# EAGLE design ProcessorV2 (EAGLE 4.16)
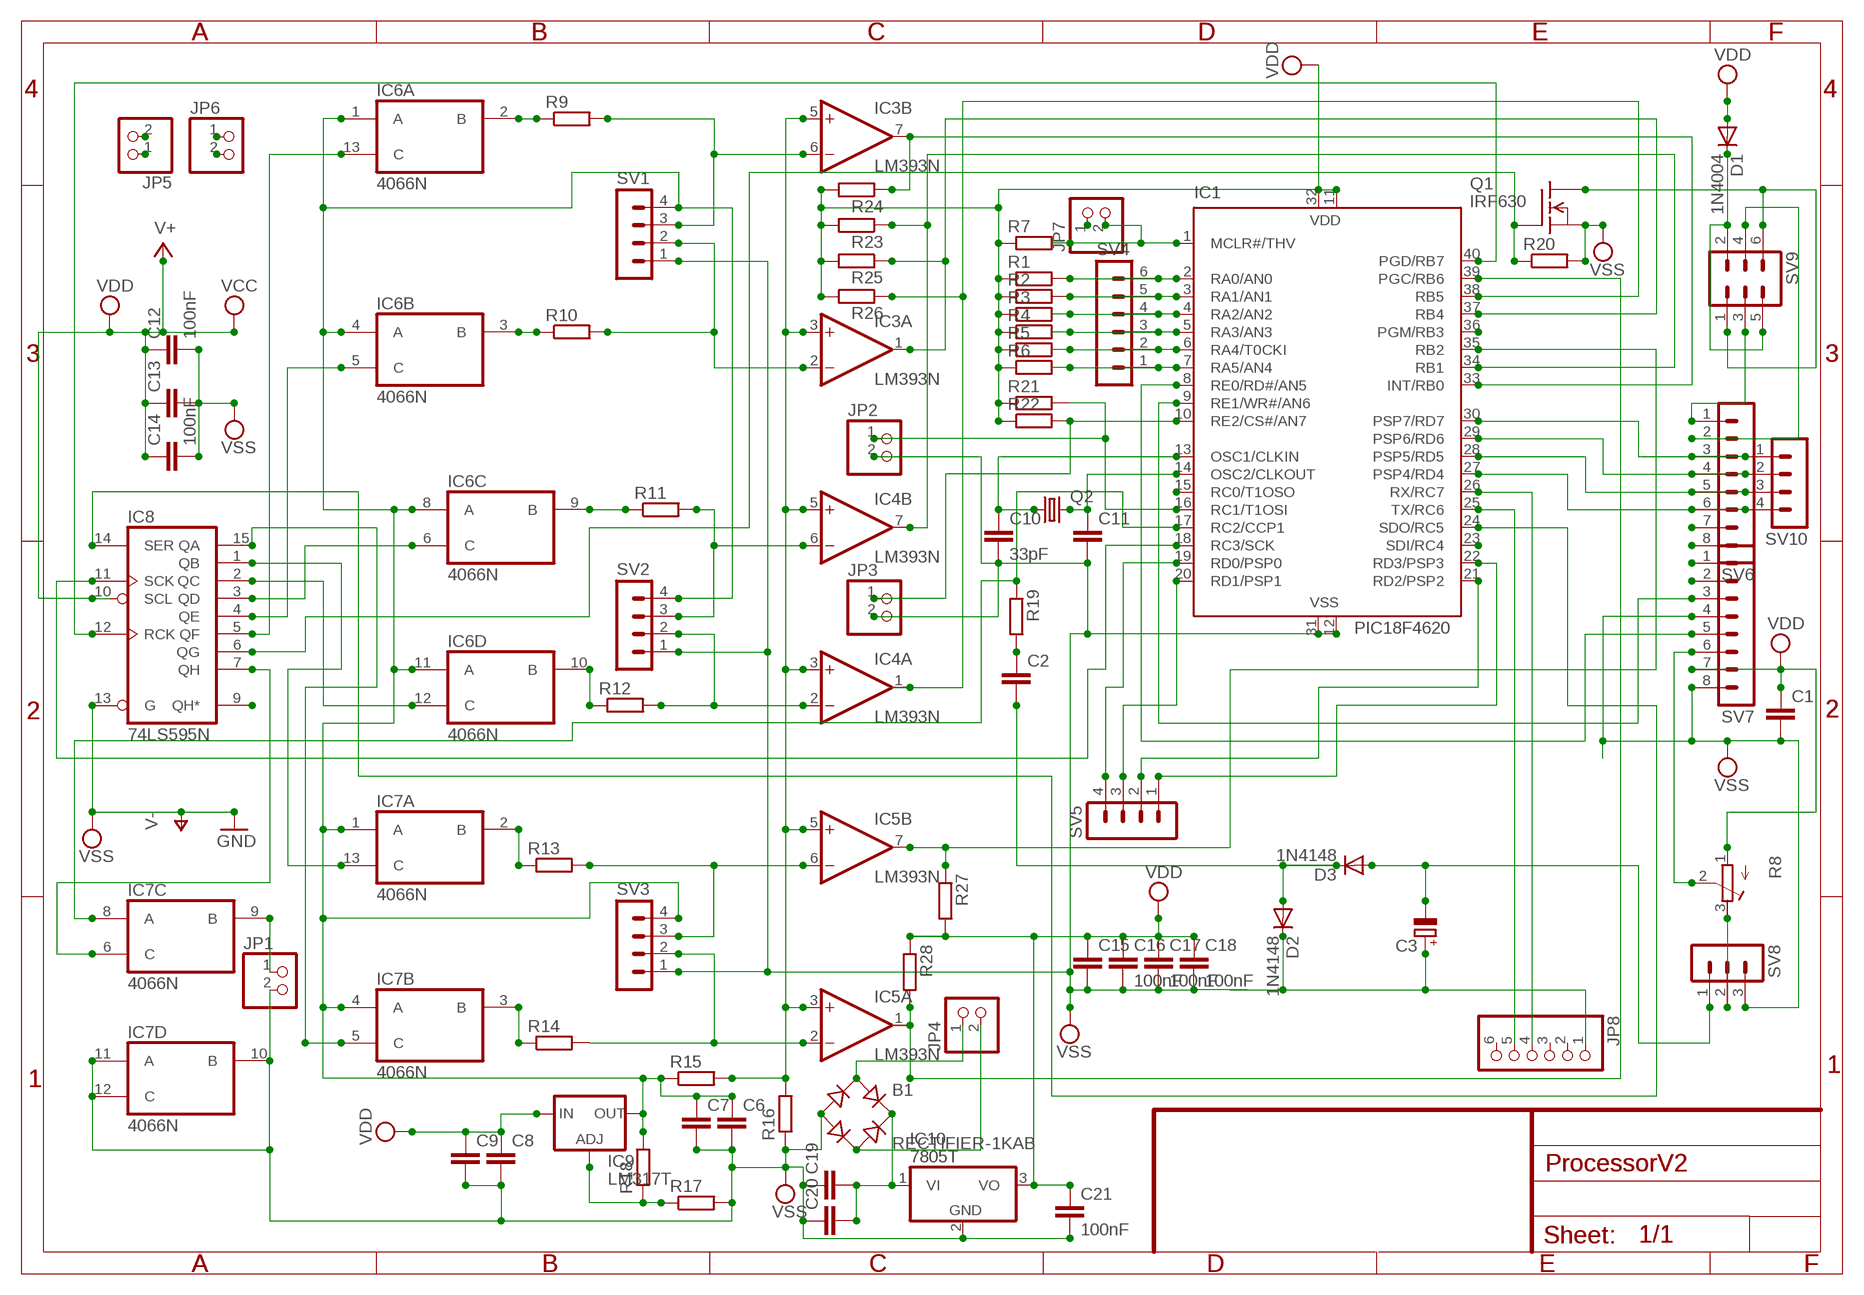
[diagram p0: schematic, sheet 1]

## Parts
B1  RECTIFIER-1KAB  [1KAB]
C1  C-EU050-024X044  [C050-024X044]
C2  C-EU025-030X050  [C025-030X050]
C3  CPOL-EUE2.5-6  [E2,5-6]
C6  C-EU050-024X044  [C050-024X044]
C7  C-EU050-024X044  [C050-024X044]
C8  C-EU050-024X044  [C050-024X044]
C9  C-EU050-024X044  [C050-024X044]
C10  33pF  C-EU050-024X044  [C050-024X044]
C11  C-EU050-024X044  [C050-024X044]
C12  100nF  C-EU050-024X044  [C050-024X044]
C13  C-EU050-024X044  [C050-024X044]
C14  100nF  C-EU050-024X044  [C050-024X044]
C15  C-EU050-024X044  [C050-024X044]
C16  100nF  C-EU050-024X044  [C050-024X044]
C17  100nF  C-EU050-024X044  [C050-024X044]
C18  100nF  C-EU050-024X044  [C050-024X044]
C19  C-EU050-024X044  [C050-024X044]
C20  C-EU050-024X044  [C050-024X044]
C21  100nF  C-EU050-024X044  [C050-024X044]
D1  1N4004  [DO41-10]
D2  1N4148  [DO35-10]
D3  1N4148  [DO35-10]
IC1  PIC18F4620  PIC16F874P  [DIL40]
IC3  LM393N  [DIL08]
IC4  LM393N  [DIL08]
IC5  LM393N  [DIL08]
IC6  4066N  [DIL14]
IC7  4066N  [DIL14]
IC8  74LS595N  [DIL16]
IC9  LM317T  LM317TL  [317TL]
IC10  7805T  [TO220H]
JP1  PINHD-1X2  [1X02]
JP2  PINHD-1X2  [1X02]
JP3  PINHD-1X2  [1X02]
JP4  PINHD-1X2  [1X02]
JP5  PINHD-1X2  [1X02]
JP6  PINHD-1X2  [1X02]
JP7  PINHD-1X2  [1X02]
JP8  PINHD-1X6  [1X06]
Q1  IRF630  IRF620  [TO220]
Q2  CRYTALHC49S  [HC49/S]
R1  R-EU_0207/10  [0207/10]
R2  R-EU_0207/10  [0207/10]
R3  R-EU_0207/10  [0207/10]
R4  R-EU_0207/10  [0207/10]
R5  R-EU_0207/10  [0207/10]
R6  R-EU_0207/10  [0207/10]
R7  R-EU_0207/10  [0207/10]
R8  R-TRIMM64Y  [RTRIM64Y]
R9  R-EU_0207/10  [0207/10]
R10  R-EU_0207/10  [0207/10]
R11  R-EU_0207/10  [0207/10]
R12  R-EU_0207/10  [0207/10]
R13  R-EU_0207/10  [0207/10]
R14  R-EU_0207/10  [0207/10]
R15  R-EU_0207/10  [0207/10]
R16  R-EU_0207/10  [0207/10]
R17  R-EU_0207/10  [0207/10]
R18  R-EU_0207/10  [0207/10]
R19  R-EU_0207/10  [0207/10]
R20  R-EU_0207/10  [0207/10]
R21  R-EU_0207/10  [0207/10]
R22  R-EU_0207/10  [0207/10]
R23  R-EU_0204/7  [0204/7]
R24  R-EU_0204/7  [0204/7]
R25  R-EU_0204/7  [0204/7]
R26  R-EU_0204/7  [0204/7]
R27  R-EU_0204/7  [0204/7]
R28  R-EU_0204/7  [0204/7]
SV1  MA04-1  [MA04-1]
SV2  MA04-1  [MA04-1]
SV3  MA04-1  [MA04-1]
SV4  MA06-1  [MA06-1]
SV5  MA04-1  [MA04-1]
SV6  MA08-1  [MA08-1]
SV7  MA08-1  [MA08-1]
SV8  MA03-1  [MA03-1]
SV9  MA03-2  [MA03-2]
SV10  MA04-1  [MA04-1]

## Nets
N$1: IC1.10(RE2/CS#/AN7) JP3.1 R22.2
N$2: C6.1 C7.1 IC6.1(A:A) IC6.4(B:A) IC6.8(C:A) IC6.11(D:A) IC7.1(A:A) IC7.4(B:A) IC9.2(OUT) R15.1 R18.2 SV1.4 SV2.4 SV3.4
N$3: D1.C SV9.2 SV9.5
N$4: IC1.17(RC2/CCP1) IC7.8(C:A) R19.1
N$6: IC1.20(RD1/PSP1) SV5.3
N$7: IC1.18(RC3/SCK) IC8.11(SCK)
N$8: IC1.19(RD0/PSP0) SV5.4
N$9: IC1.21(RD2/PSP2) SV5.2
N$10: IC1.22(RD3/PSP3) SV5.1
N$11: B1.+ C19.2 C20.2 IC10.1(VI)
N$12: IC1.3(RA1/AN1) R2.2 SV4.5
N$13: IC6.13(A:C) IC8.5(QF)
N$14: B1.AC1 JP4.1
N$15: B1.AC2 JP4.2
N$16: IC1.35(RB2) IC5.7(B:OUT) R27.1
N$17: IC1.2(RA0/AN0) R1.2 SV4.6
N$19: IC1.26(RX/RC7) JP8.4
N$20: IC1.4(RA2/AN2) R3.2 SV4.4
N$21: IC1.5(RA3/AN3) R4.2 SV4.3
N$22: IC1.6(RA4/T0CKI) R5.2 SV4.2
N$23: IC1.7(RA5/AN4) R6.2 SV4.1
N$24: IC1.25(TX/RC6) JP8.5
N$25: IC1.24(SDO/RC5) IC8.14(SER)
N$26: IC1.1(MCLR#/THV) JP7.2 R7.2
N$27: IC6.9(C:B) R11.1
N$28: IC7.5(B:C) IC8.15(QA)
N$29: IC1.15(RC0/T1OSO)
N$31: IC1.30(PSP7/RD7) SV6.3 SV10.1
N$32: IC1.36(PGM/RB3) JP5.2
N$33: IC1.29(PSP6/RD6) SV6.4 SV10.2
N$34: IC1.9(RE1/WR#/AN6) SV7.3
N$35: IC1.23(SDI/RC4) JP6.1
N$36: SV6.1 SV9.3
N$37: SV6.2 SV9.4
N$38: IC7.9(C:B) JP1.1
N$39: IC9.1(ADJ) R17.1 R18.1
N$40: IC1.28(PSP5/RD5) SV6.5 SV10.3
N$41: IC1.27(PSP4/RD4) SV6.6 SV10.4
N$42: SV6.7
N$43: SV6.8
N$44: SV7.1
N$45: SV7.2
N$46: IC8.6(QG) Q1.1(G) R20.1
N$47: C2.1 R19.2
N$48: Q1.2(D) SV9.1 SV9.6
N$49: R8.3(A) SV8.2
N$55: IC8.9(QH*)
N$56: IC7.6(C:C) IC8.7(QH)
N$57: IC1.40(PGD/RB7) IC8.12(RCK)
N$58: C3.- D3.A SV8.1
N$59: IC6.5(B:C) IC8.4(QE)
N$60: IC6.6(C:C) IC8.3(QD)
N$61: IC6.12(D:C) IC8.2(QC)
N$62: IC7.13(A:C) IC8.1(QB)
N$63: C2.2 D2.A D3.C
N$65: IC1.16(RC1/T1OSI) JP2.1 R21.2
N$66: IC6.3(B:B) R10.1
N$70: IC1.33(INT/RB0) IC3.7(B:OUT) R24.1
N$71: IC1.34(RB1) IC4.7(B:OUT) R23.1
N$72: IC6.10(D:B) R12.1
N$73: IC1.37(RB4) IC3.1(A:OUT) R25.1
N$74: IC7.2(A:B) R13.1
N$76: IC1.38(RB5) IC4.1(A:OUT) R26.1
N$78: IC7.3(B:B) R14.1
N$81: IC1.39(PGC/RB6) IC5.1(A:OUT) R28.2
N$88: C10.1 IC1.13(OSC1/CLKIN) Q2.1
N$93: C11.1 IC1.14(OSC2/CLKOUT) Q2.2
N$101: IC1.8(RE0/RD#/AN5) SV7.5
N$102: IC3.3(A:+IN) IC3.5(B:+IN) IC4.3(A:+IN) IC4.5(B:+IN) IC5.3(A:+IN) IC5.5(B:+IN) R15.2 R16.2
N$103: IC6.2(A:B) R9.1
N$111: IC3.6(B:-IN) R9.2 SV1.3
N$113: IC3.2(A:-IN) R10.2 SV1.2
N$115: IC4.6(B:-IN) R11.2 SV2.3
N$116: IC4.2(A:-IN) R12.2 SV2.2
N$119: IC5.6(B:-IN) R13.2 SV3.3
N$128: IC5.2(A:-IN) R14.2 SV3.2
N$136: R8.2(S) SV7.6
VDD: C1.1 C8.1 C9.1 C12.1 C13.1 C14.1 C15.1 C16.1 C17.1 C18.1 C21.1 D1.A IC1.11(VDD) IC1.32(VDD) IC8.10(SCL) IC9.3(IN) IC10.3(VO) R1.1 R2.1 R3.1 R4.1 R5.1 R6.1 R7.1 R8.1(E) R21.1 R22.1 R23.2 R24.2 R25.2 R26.2 R27.2 R28.1 SV7.7 ; supply symbol labelled V+, VCC
VSS: B1.- C1.2 C3.+ C6.2 C7.2 C8.2 C9.2 C10.2 C11.2 C12.2 C13.2 C14.2 C15.2 C16.2 C17.2 C18.2 C19.1 C20.1 C21.2 D2.C IC1.12(VSS) IC1.31(VSS) IC7.10(D:B) IC7.11(D:A) IC7.12(D:C) IC8.13(G) IC10.2(GND) JP1.2 JP2.2 JP3.2 JP5.1 JP6.2 JP7.1 JP8.1 Q1.3(S) R16.1 R17.2 R20.2 SV1.1 SV2.1 SV3.1 SV7.4 SV7.8 SV8.3 ; supply symbol labelled V-, GND
Unconnected: JP8.2 JP8.3 JP8.6

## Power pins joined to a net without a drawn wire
VDD: IC3.8(P:V+) IC4.8(P:V+) IC5.8(P:V+) IC6.14(P:VDD) IC7.14(P:VDD) IC8.16(VCC)
VSS: IC3.4(P:V-) IC4.4(P:V-) IC5.4(P:V-) IC6.7(P:VSS) IC7.7(P:VSS) IC8.8(GND)

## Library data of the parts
B1 = rectifier:RECTIFIER-: Rectifier
C1 C2 C6-C21 = rcl:C-EU: CAPACITOR, European symbol
C3 = rcl:CPOL-EU: POLARIZED CAPACITOR, European symbol
D1 = diode:1N4004: DIODE
D2 D3 = diode:1N4148: DIODE
IC1 = microchip:PIC16F87*: MICROCONTROLLER
IC3-IC5 = linear:LM393: COMPARATOR
IC6 IC7 = 40xx:4066: Quad bilateral ANALOG SWITCH
IC8 = 74xx-us:74*595: 8-bit SHIFT REGISTER, output latch
IC9 = v-reg:LM317TL: VOLTAGE REGULATOR
IC10 = linear:78*: Positive VOLTAGE REGULATOR
JP1-JP7 = pinhead:PINHD-1X2: PIN HEADER
JP8 = pinhead:PINHD-1X6: PIN HEADER
Q1 = transistor-fet:IRF620: N-Channel Enhancement MOSFET (HEXFET); 200V; 5,2A; 0,8Ohm
Q2 = crystal:CRYTAL: CRYSTAL
R1-R7 R9-R28 = rcl:R-EU_: RESISTOR, European symbol
R8 = rcl:R-TRIMM: Trimm resistor
SV1-SV3 SV5 SV10 = con-lstb:MA04-1: PIN HEADER
SV4 = con-lstb:MA06-1: PIN HEADER
SV6 SV7 = con-lstb:MA08-1: PIN HEADER
SV8 = con-lstb:MA03-1: PIN HEADER
SV9 = con-lstb:MA03-2: PIN HEADER

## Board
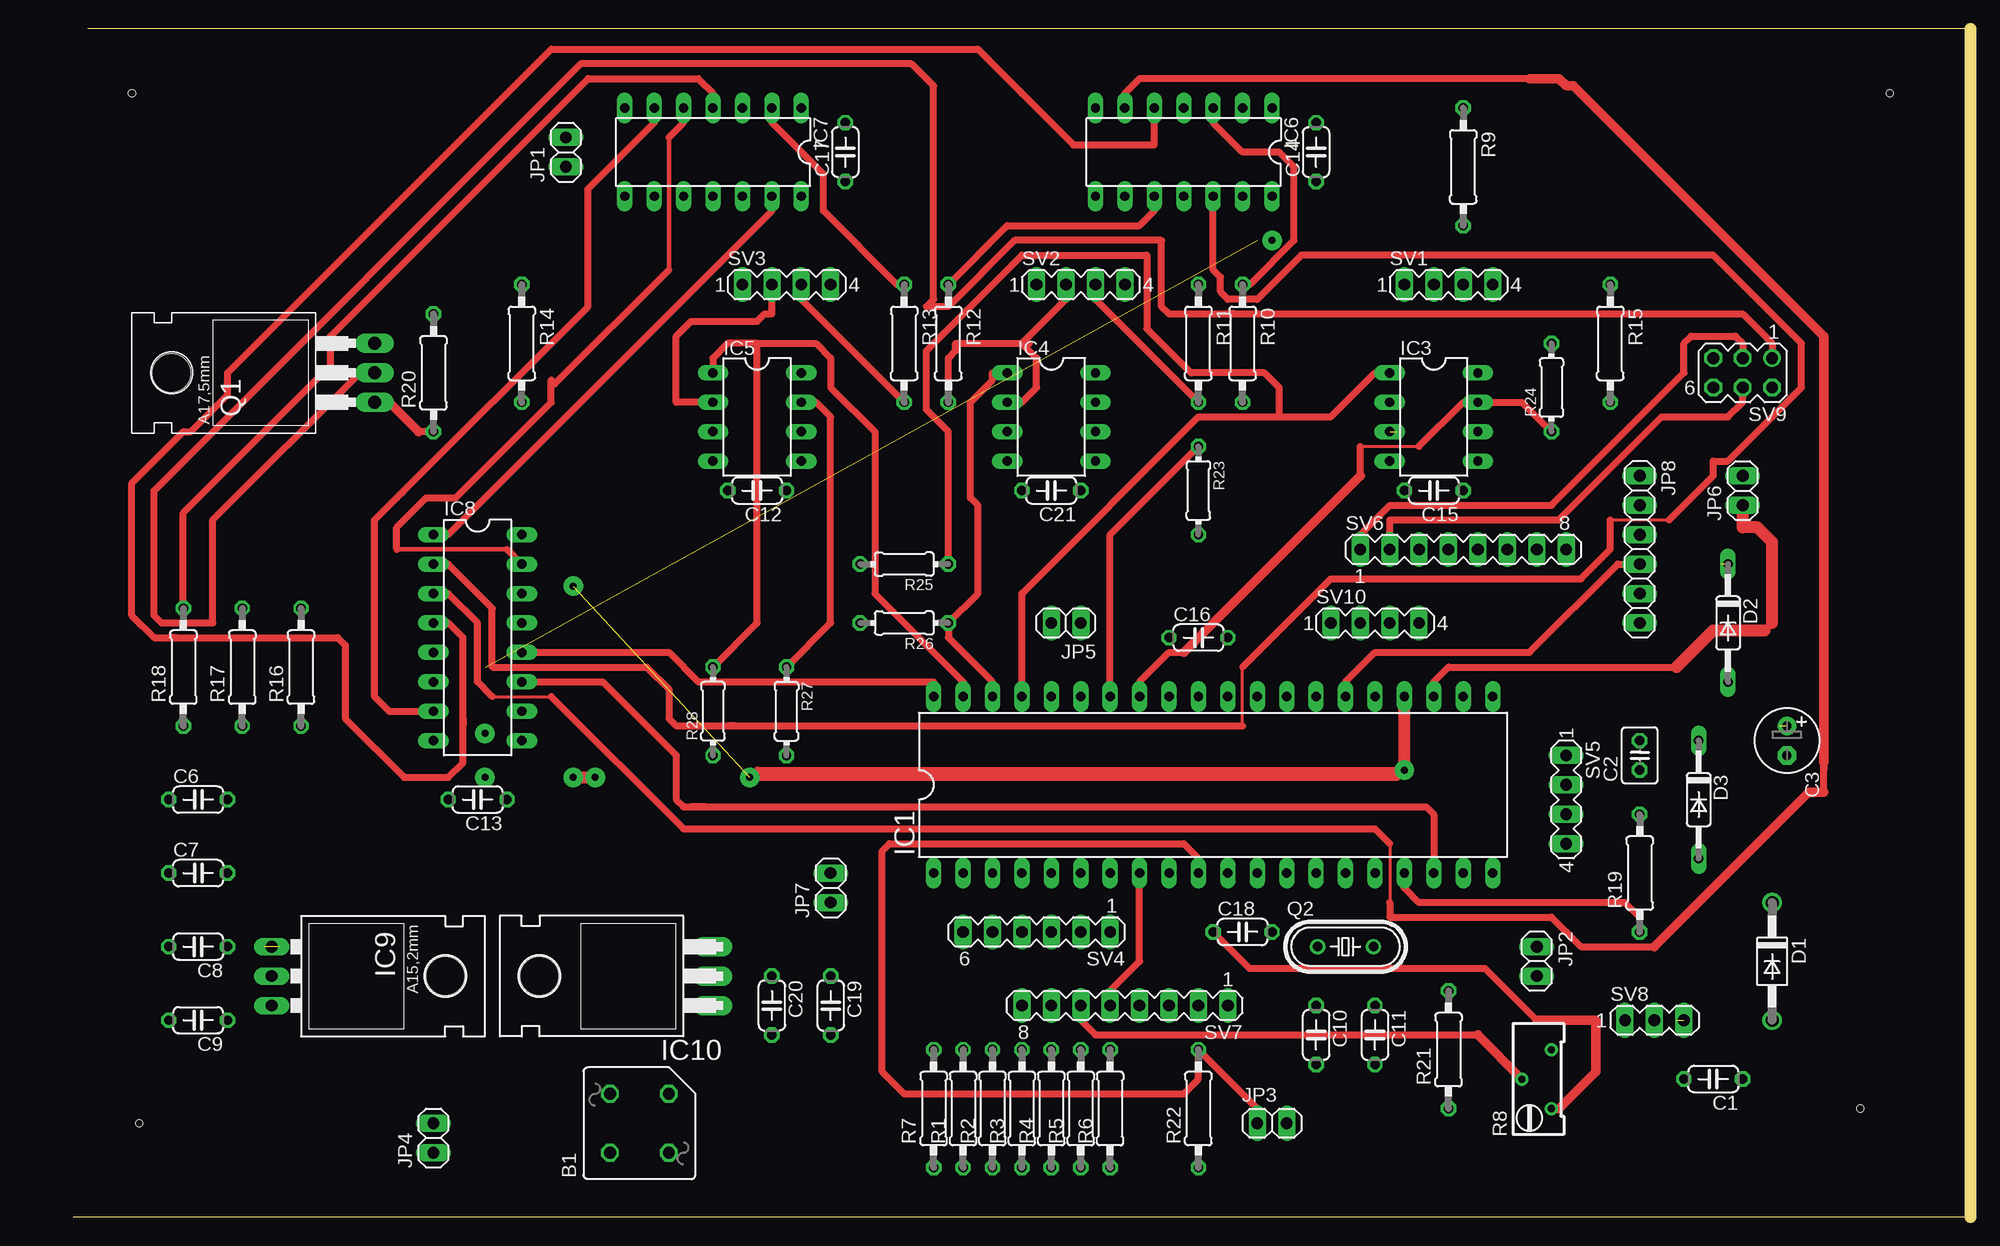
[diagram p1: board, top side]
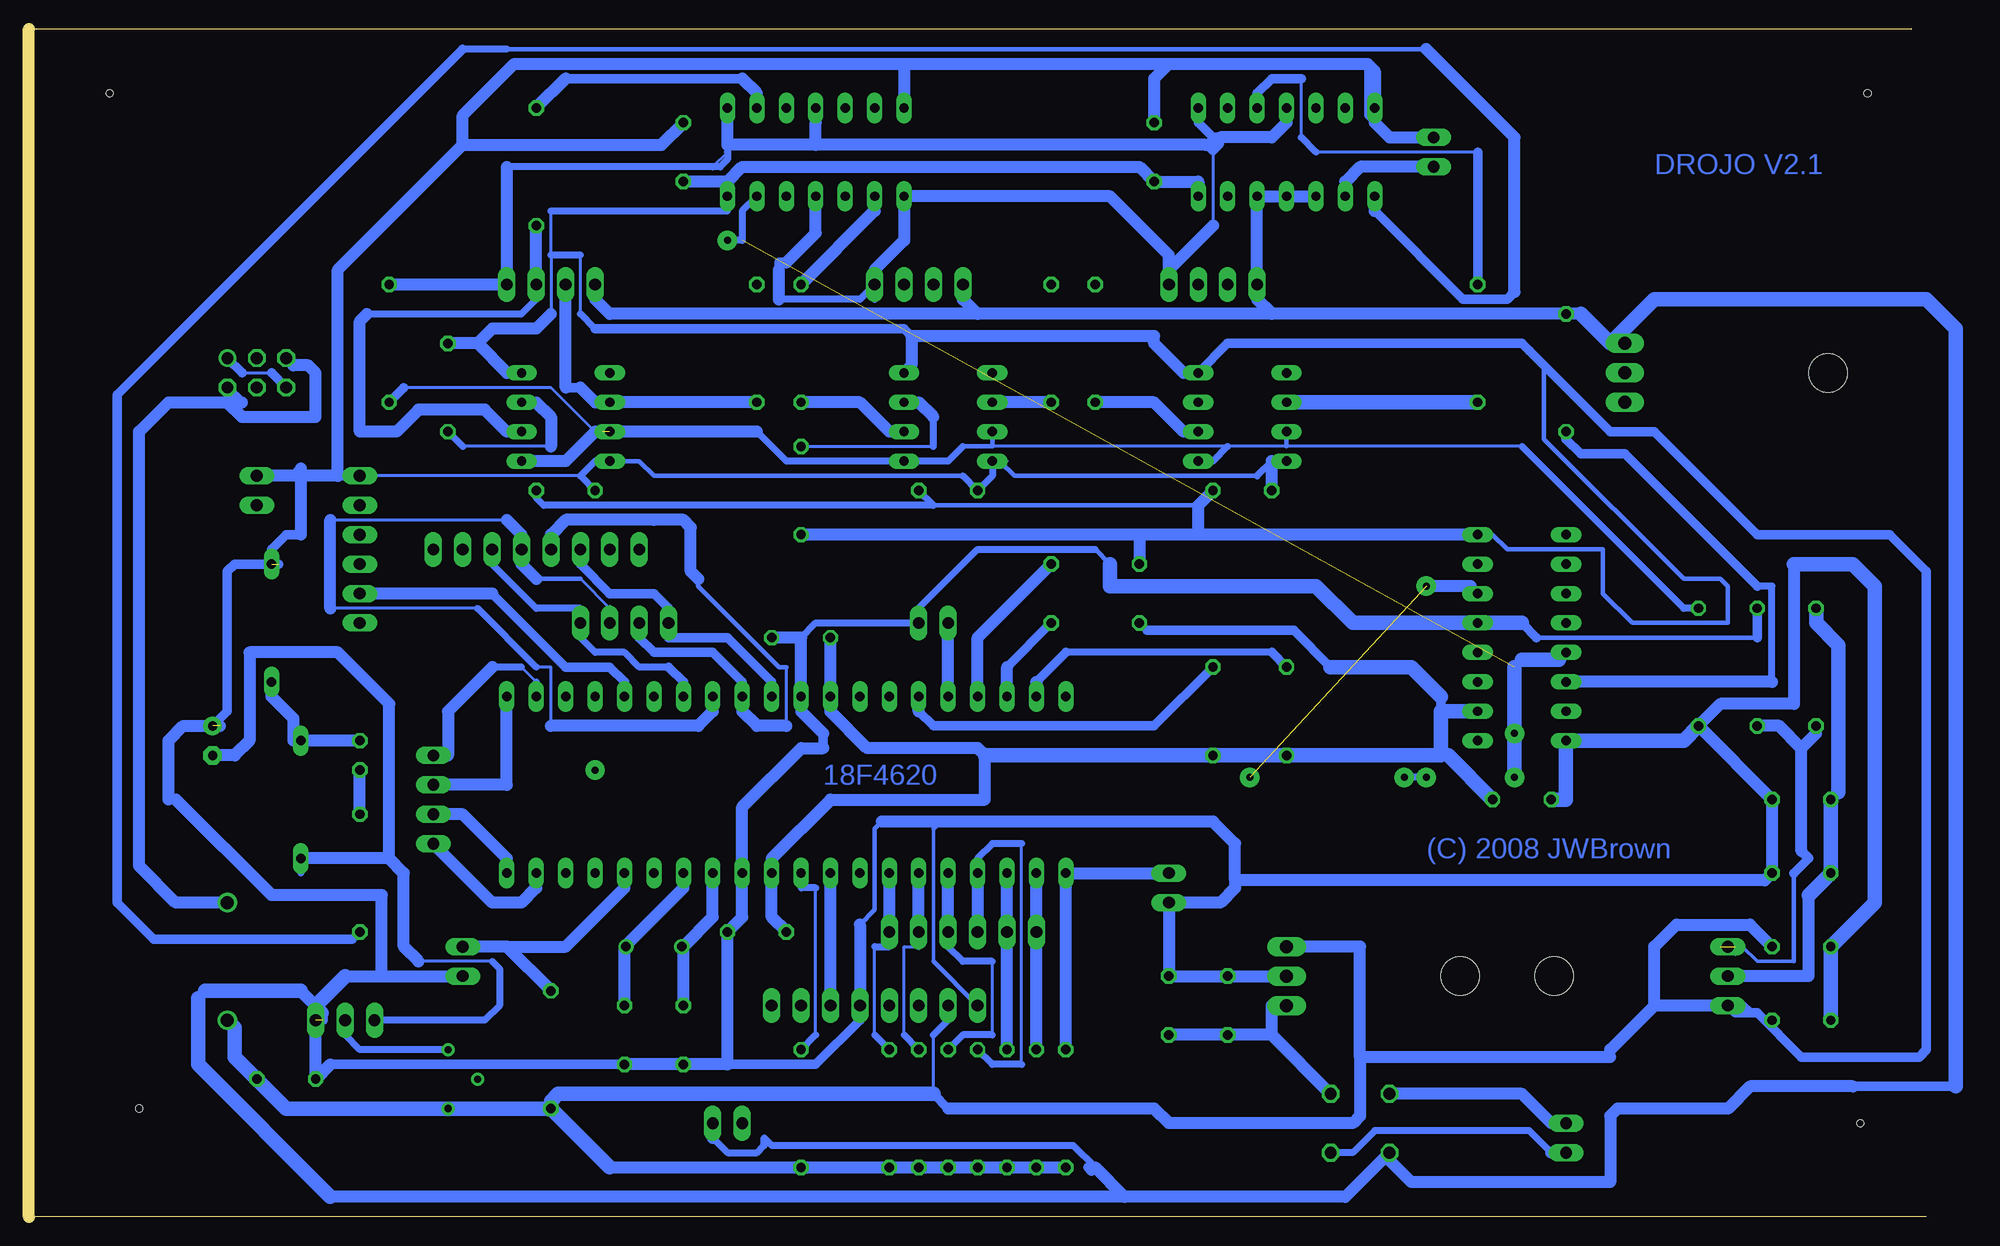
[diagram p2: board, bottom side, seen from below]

Size 163.81 x 102.54 mm. Coordinates in mm from the lower left corner, seen from the top.
Outline: 0,0 163.81,0 163.81,102.54 1.27,102.54
Copper layers (1*16): Top 0.035mm / dielectric 1.5mm / Bottom 0.035mm
Design rules "default": minimum track width 10mil, minimum drill 24mil, track to track 8mil, track to pad 8mil, pad to pad 8mil, via to via 8mil, smd to smd 8mil, copper to edge 40mil, drill to drill 8mil, minimum pad ring 10mil, minimum via ring 8mil, stop-mask expansion 4mil, vias tented up to drill 0mil, thermal gap 10mil
Holes 0.6 mm at 5.71,8.09 154.3,9.36 156.84,96.99 5.08,96.99

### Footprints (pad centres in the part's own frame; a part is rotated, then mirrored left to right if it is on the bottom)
1KAB = drill 1.016 octagon: + 2.54,-2.54; - -2.54,2.54; AC1 -2.54,-2.54; AC2 2.54,2.54
C050-024X044 = drill 0.813 octagon: 1 -2.54,0; 2 2.54,0
C025-030X050 = drill 0.813 octagon: 1 -1.27,0; 2 1.27,0
E2,5-6 = drill 0.813 pad 1.6 round: + -1.27,0 | drill 0.813 pad 1.6 octagon: - 1.27,0
DO41-10 = drill 1.118 round: A 5.08,0; C -5.08,0
DO35-10 = drill 0.813 long: A 5.08,0; C -5.08,0
DIL40 = drill 0.813 long: 1 -24.13,-7.62; 2 -21.59,-7.62; 3 -19.05,-7.62; 4 -16.51,-7.62; 5 -13.97,-7.62; 6 -11.43,-7.62; 7 -8.89,-7.62; 8 -6.35,-7.62; 9 -3.81,-7.62; 10 -1.27,-7.62; 11 1.27,-7.62; 12 3.81,-7.62; 13 6.35,-7.62; 14 8.89,-7.62; 15 11.43,-7.62; 16 13.97,-7.62; 17 16.51,-7.62; 18 19.05,-7.62; 19 21.59,-7.62; 20 24.13,-7.62; 21 24.13,7.62; 22 21.59,7.62; 23 19.05,7.62; 24 16.51,7.62; 25 13.97,7.62; 26 11.43,7.62; 27 8.89,7.62; 28 6.35,7.62; 29 3.81,7.62; 30 1.27,7.62; 31 -1.27,7.62; 32 -3.81,7.62; 33 -6.35,7.62; 34 -8.89,7.62; 35 -11.43,7.62; 36 -13.97,7.62; 37 -16.51,7.62; 38 -19.05,7.62; 39 -21.59,7.62; 40 -24.13,7.62
DIL08 = drill 0.813 long: 1 -3.81,-3.81; 2 -1.27,-3.81; 3 1.27,-3.81; 4 3.81,-3.81; 5 3.81,3.81; 6 1.27,3.81; 7 -1.27,3.81; 8 -3.81,3.81
DIL14 = drill 0.813 long: 1 -7.62,-3.81; 2 -5.08,-3.81; 3 -2.54,-3.81; 4 0,-3.81; 5 2.54,-3.81; 6 5.08,-3.81; 7 7.62,-3.81; 8 7.62,3.81; 9 5.08,3.81; 10 2.54,3.81; 11 0,3.81; 12 -2.54,3.81; 13 -5.08,3.81; 14 -7.62,3.81
DIL16 = drill 0.813 long: 1 -8.89,-3.81; 2 -6.35,-3.81; 3 -3.81,-3.81; 4 -1.27,-3.81; 5 1.27,-3.81; 6 3.81,-3.81; 7 6.35,-3.81; 8 8.89,-3.81; 9 8.89,3.81; 10 6.35,3.81; 11 3.81,3.81; 12 1.27,3.81; 13 -1.27,3.81; 14 -3.81,3.81; 15 -6.35,3.81; 16 -8.89,3.81
317TL = drill 1.016 long: 1 -2.54,-3.81; 2 0,-3.81; 3 2.54,-3.81 | hole 3.302: 0,11.176
TO220H = drill 1.118 long: 1 -2.54,-10.16; 2 0,-10.16; 3 2.54,-10.16 | hole 3.302: 0,4.826
1X02 = drill 1.016 long: 1 -1.27,0; 2 1.27,0
1X06 = drill 1.016 long: 1 -6.35,0; 2 -3.81,0; 3 -1.27,0; 4 1.27,0; 5 3.81,0; 6 6.35,0
TO220 = drill 1.118 long: 1 -2.54,-6.35; 2 0,-6.35; 3 2.54,-6.35 | hole 3.302: 0,11.176
HC49/S = drill 0.813 round: 1 -2.413,0; 2 2.413,0
0207/10 = drill 0.813 octagon: 1 -5.08,0; 2 5.08,0
RTRIM64Y = drill 0.61 round: 1 0,-2.54; 2 -2.54,0; 3 0,2.54
0204/7 = drill 0.813 octagon: 1 -3.81,0; 2 3.81,0
MA04-1 = drill 1.016 long: 1 -3.81,0; 2 -1.27,0; 3 1.27,0; 4 3.81,0
MA06-1 = drill 1.016 long: 1 -6.35,0; 2 -3.81,0; 3 -1.27,0; 4 1.27,0; 5 3.81,0; 6 6.35,0
MA08-1 = drill 1.016 long: 1 -8.89,0; 2 -6.35,0; 3 -3.81,0; 4 -1.27,0; 5 1.27,0; 6 3.81,0; 7 6.35,0; 8 8.89,0
MA03-1 = drill 1.016 long: 1 -2.54,0; 2 0,0; 3 2.54,0
MA03-2 = drill 1.016 round: 1 -2.54,-1.27 | drill 1.016 octagon: 2 -2.54,1.27; 3 0,-1.27; 4 0,1.27; 5 2.54,-1.27; 6 2.54,1.27

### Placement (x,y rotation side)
B1  48.89,8.09 90 top
C1  141.6,11.9 180 top
C2  135.25,39.84 90 top
C3  147.95,41.11 270 top
C6  10.79,36.03 0 top
C7  10.79,29.68 0 top
C8  10.79,23.33 180 top
C9  10.79,16.98 180 top
C10  107.31,15.71 270 top
C11  112.39,15.71 270 top
C12  59.05,62.7 180 top
C13  34.92,36.03 180 top
C14  107.31,91.91 90 top
C15  117.47,62.7 180 top
C16  97.15,50 0 top
C17  66.67,91.91 90 top
C18  100.96,24.6 0 top
C19  65.4,18.25 270 top
C20  60.32,18.25 270 top
C21  84.45,62.7 180 top
D1  146.68,22.06 270 top
D2  142.87,51.27 270 top
D3  140.33,36.03 270 top
IC1  98.42,37.3 0 top
IC3  117.47,69.05 270 top
IC4  84.45,69.05 270 top
IC5  59.05,69.05 270 top
IC6  95.88,91.91 180 top
IC7  55.24,91.91 180 top
IC8  34.92,50 270 top
IC9  20.95,20.79 270 top
IC10  45.08,20.79 90 top
JP1  42.54,91.91 90 top
JP2  126.36,22.06 270 top
JP3  103.5,8.09 0 top
JP4  31.11,6.82 90 top
JP5  85.72,51.27 180 top
JP6  144.14,62.7 90 top
JP7  65.4,28.41 90 top
JP8  135.25,57.62 270 top
Q1  19.68,72.86 90 top
Q2  109.85,23.33 0 top
R1  76.83,9.36 90 top
R2  79.37,9.36 90 top
R3  81.91,9.36 90 top
R4  84.45,9.36 90 top
R5  86.99,9.36 90 top
R6  89.53,9.36 90 top
R7  74.29,9.36 90 top
R8  127.63,11.9 0 top
R9  120.01,90.64 270 top
R10  100.96,75.4 270 top
R11  97.15,75.4 270 top
R12  75.56,75.4 270 top
R13  71.75,75.4 270 top
R14  38.73,75.4 270 top
R15  132.71,75.4 270 top
R16  19.68,47.46 90 top
R17  14.6,47.46 90 top
R18  9.52,47.46 90 top
R19  135.25,29.68 90 top
R20  31.11,72.86 90 top
R21  118.74,14.44 90 top
R22  97.15,9.36 90 top
R23  97.15,62.7 270 top
R24  127.63,71.59 90 top
R25  71.75,56.35 180 top
R26  71.75,51.27 180 top
R27  61.59,43.65 270 top
R28  55.24,43.65 90 top
SV1  118.74,80.48 0 top
SV2  86.99,80.48 0 top
SV3  61.59,80.48 0 top
SV4  83.18,24.6 180 top
SV5  128.9,36.03 270 top
SV6  120.01,57.62 0 top
SV7  90.8,18.25 180 top
SV8  136.52,16.98 0 top
SV9  144.14,72.86 180 top
SV10  112.39,51.27 0 top

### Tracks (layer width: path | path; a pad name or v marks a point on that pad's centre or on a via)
N$1
  Top 0.61: JP3.1 102.23,9.36 R22.2 97.15,11.9 95.88,10.63 71.75,10.63 69.84,12.54 69.84,31.59 70.48,32.22 95.88,32.22 97.15,30.95 IC1.10
  Bottom 0.254: 95.88,15.71 95.88,28.41
  Bottom 0.61: R22.2 95.88,15.71 | 95.88,28.41 97.15,28.41 IC1.10
N$2
  Top 0.61: IC7.4 55.24,96.99 53.97,98.26 44.45,98.26 22.22,76.04 22.22,73.5 9.52,60.79 R18.2
  Bottom 0.254: IC6.11 95.88,86.83 | 103.5,91.91 104.77,90.64 | 61.59,91.91 61.59,85.56
  Bottom 0.406: C6.1 7.62,36.66
  Bottom 0.61: 90.8,79.21 SV2.4 92.07,79.21 99.05,79.21 | IC7.4 55.24,94.45 | 62.86,94.45 IC7.1 | 95.88,94.45 IC6.4 | 103.5,94.45 IC6.1 | 122.55,90.64 104.77,90.64 104.13,90.64 103.5,91.28 103.5,92.55 103.5,91.91 | 61.59,93.18 62.23,92.55 61.59,91.91 60.96,92.55 60.96,93.18 61.59,92.55
  Bottom 0.813: 60.96,93.18 61.59,93.18 62.86,94.45 | 65.4,81.75 SV3.4 | 98.42,82.39 99.05,82.39 99.05,81.75 99.05,81.12
  Bottom 1.016: R15.1 SV1.4 122.55,90.64 | 55.24,94.45 56.51,93.18 60.96,93.18 | 61.59,85.56 65.4,81.75 | SV3.4 65.4,83.02 70.48,88.1 IC6.8 88.26,84.29 90.8,81.75 SV2.4 | IC6.11 95.88,84.93 98.42,82.39 | 99.05,79.21 99.05,81.75 | 62.23,92.55 95.88,92.55 | 95.88,92.55 95.88,94.45 | 103.5,94.45 103.5,92.55 95.88,92.55 | 10.16,27.77 10.16,20.79 IC9.2
  Bottom 1.27: 10.16,27.77 C7.1 C6.1 | 7.62,36.66 7.62,49.36 9.52,51.27 R18.2
N$3
  Bottom 0.61: SV9.2 146.68,70.32
  Bottom 0.813: 145.41,70.32 SV9.2 | 149.22,70.32 150.49,70.32
  Bottom 1.016: 145.41,70.32 149.22,70.32 151.76,70.32 154.3,67.78 154.3,30.31 151.12,27.14 D1.C | SV9.5 140.97,73.5 139.69,73.5 139.06,72.86 139.06,69.05 145.41,69.05 146.68,70.32
N$4
  Top 0.61: IC1.17 114.93,28.41 116.2,27.14 133.98,27.14 135.25,25.87 R19.1
  Bottom 0.254: 38.1,79.21 37.46,79.21
  Bottom 0.406: 43.18,100.8 122.55,100.8
  Bottom 0.61: 135.88,23.96 R19.1 | 122.55,100.8 126.36,100.8
  Bottom 0.813: 47.62,86.83 40,79.21 38.1,79.21 36.19,79.21 35.55,79.84 | 135.88,23.96 153.03,23.96 156.2,27.14 156.2,70.95 126.36,100.8
  Bottom 1.016: 47.62,86.83 IC7.8 | 43.18,100.8 35.55,93.18 35.55,79.84
N$5  (via drill 0.6 pad 1.68)
  Top 1.016: v43.18,37.93 v45.08,37.93
  Bottom 0.61: v43.18,37.93 v45.08,37.93
N$6
  Bottom 1.016: IC1.20 122.55,30.95 126.36,34.76 SV5.3
N$7
  Top 0.254: 117.47,30.95 IC1.18
  Top 0.61: 117.47,30.95 117.47,34.76 116.83,35.39 54.61,35.39 | 54.61,35.39 53.34,35.39 | IC8.11 45.72,46.19 52.07,39.84 52.07,36.03 52.7,35.39 54.61,35.39
N$8
  Bottom 1.016: SV5.4 123.82,27.14 121.28,27.14 120.01,28.41 IC1.19
N$9
  Bottom 1.016: IC1.21 122.55,37.3 SV5.2
N$10
  Bottom 0.254: 120.01,46.19 121.28,47.46
  Bottom 0.61: 121.28,47.46 123.82,47.46 | IC1.22 120.01,46.19
  Bottom 1.016: 123.82,47.46 127.63,43.65 127.63,39.84 SV5.1
N$11
  Bottom 1.016: C19.2 C20.2 56.51,15.71 | B1.+ 56.51,15.71 | 56.51,15.71 56.51,18.25 IC10.1
N$12
  Bottom 1.016: R2.2 SV4.5 IC1.3
N$13  (1 unrouted)
  Bottom 0.61: 35.55,47.46 34.92,48.09 | IC6.13 102.23,86.83 102.23,84.29 103.5,84.29
  Bottom 1.016: 31.74,48.09 IC8.5
  Bottom 1.27: 34.92,48.09 31.74,48.09 | 35.55,37.93 35.55,47.46
N$14
  Bottom 0.61: 32.38,5.55 34.29,7.46 47.62,7.46 49.53,5.55 B1.AC1
  Bottom 1.016: JP4.1 32.38,5.55
N$15
  Bottom 1.016: B1.AC2 34.92,10.63 32.38,8.09 JP4.2
N$16
  Top 0.61: R27.1 65.4,51.27 65.4,69.05 64.13,70.32 IC5.7
  Bottom 0.813: R27.1 66.67,42.38 85.72,42.38 86.99,43.65
  Bottom 1.016: 86.99,43.65 IC1.35
N$17
  Bottom 1.016: R1.2 SV4.6 IC1.2
N$19
  Top 0.61: IC1.26 109.85,46.19 112.39,48.73 125.72,48.73 133.34,56.35 JP8.4
N$20
  Bottom 0.254: 78.1,13.17 78.1,32.22
  Bottom 0.61: R3.2 80.64,13.17 78.1,13.17 | 78.1,32.22 80.64,32.22 81.91,30.95 IC1.4
  Bottom 1.016: IC1.4 SV4.4
N$21
  Bottom 0.254: 80.64,15.71 80.64,22.06
  Bottom 0.61: R4.2 83.18,15.71 80.64,15.71 | 80.64,22.06 83.18,22.06 84.45,23.33 SV4.3
  Bottom 1.016: SV4.3 IC1.5
N$22
  Bottom 0.254: 88.26,15.71 88.26,23.33 86.99,23.33
  Bottom 0.61: R5.2 88.26,15.71 | 86.99,23.33 SV4.2
  Bottom 1.016: SV4.2 IC1.6
N$23
  Bottom 0.254: 90.8,15.71 90.8,23.33
  Bottom 0.61: R6.2 90.8,15.71 | 90.8,23.33 89.53,23.33 SV4.1
  Bottom 1.016: SV4.1 IC1.7
N$24
  Bottom 0.61: IC1.25 112.39,46.19
  Bottom 0.813: 112.39,46.19 113.66,47.46 117.47,47.46 123.82,53.81
  Bottom 1.016: 123.82,53.81 JP8.5
N$25  (1 unrouted)
  Top 0.61: 114.93,38.57 114.3,37.93 58.41,37.93
  Top 1.016: 114.93,38.57 IC1.24
  Bottom 0.406: IC8.14 39.37,54.45
  Bottom 1.016: 39.37,54.45 43.18,54.45
N$26
  Bottom 1.016: R7.2 IC1.1 JP7.2
N$27
  Bottom 0.61: 90.8,86.83 IC6.9
  Bottom 1.016: R11.1 90.8,86.83
N$28
  Top 0.406: 51.43,81.75 51.43,93.18 | 41.27,70.95 41.27,71.59 41.59,71.91 41.27,72.23 | 27.93,57.62 37.46,57.62
  Top 0.61: IC7.5 52.7,94.45 51.43,93.18 | 41.59,71.91 51.43,81.75 | 37.46,57.62 IC8.15 | 27.93,57.62 27.93,59.52 30.47,62.06 33.02,62.06 41.27,70.32 41.27,72.23
N$30  (via drill 0.6 pad 1.68)
  other vias: 35.55,41.74
N$31
  Bottom 0.254: IC1.30 99.69,46.19 | SV10.1 108.58,52.54
  Bottom 0.813: 99.69,46.19 103.5,50 108.58,50 SV10.1 | 108.58,52.54 109.85,53.81 113.66,53.81 116.2,56.35 SV6.3
N$32
  Bottom 1.016: IC1.36 JP5.2
N$33
  Bottom 0.254: IC1.29 102.23,46.19 | 98.42,42.38 98.42,47.46
  Bottom 0.406: 98.42,47.46 99.05,47.46 106.04,54.45 106.04,55.08
  Bottom 0.61: 102.23,43.65 IC1.29
  Bottom 0.813: 102.23,46.19 104.77,48.73 109.85,48.73 111.12,50 SV10.2
  Bottom 1.016: 98.42,42.38 100.96,42.38 102.23,43.65 | SV6.4 118.74,58.89 117.47,60.16 109.85,60.16 107.31,60.16 106.67,59.52 106.67,55.71 106.04,55.08
N$34
  Bottom 1.016: SV7.3 IC1.9
N$35
  Top 0.61: IC1.23 117.47,46.19 118.74,47.46 138.42,47.46 | 146.04,50.63 146.68,51.27
  Top 1.016: 138.42,47.46 141.6,50.63 146.04,50.63 | 146.68,51.27 146.68,58.25 145.41,59.52 144.14,59.52 JP6.1
N$36
  Top 0.61: SV6.1 111.12,58.89 113.66,61.43 127.63,61.43 139.06,72.86 139.06,75.4 139.69,76.04 143.5,76.04 144.14,75.4 SV9.3
N$37
  Top 0.61: SV6.2 113.66,60.16 128.27,60.16 137.16,69.05 142.87,69.05 144.14,70.32 SV9.4
N$38
  Bottom 1.016: IC7.9 50.16,89.37 48.89,90.64 JP1.1
N$39  (1 unrouted)
  Bottom 0.305: 11.43,22.06 14.6,22.06 15.87,23.33 16.5,23.33 16.5,22.7 | IC9.1 17.77,23.33
  Bottom 0.406: 11.43,22.06 11.43,29.68
  Bottom 0.813: 11.43,29.68 10.16,30.95 10.79,31.59 | 9.52,41.74 R18.1
  Bottom 1.016: 10.79,31.59 10.79,40.48 | 10.79,40.48 9.52,41.74 | 10.79,40.48 12.7,42.38 R17.1
N$40
  Bottom 0.254: 118.74,42.38 118.74,47.46 120.01,47.46 | 125.09,52.54 137.79,52.54 | 137.79,60.16 122.55,60.16 | 116.2,55.08 113.66,52.54
  Bottom 0.406: 120.01,55.08 116.2,55.08
  Bottom 0.61: 120.01,47.46 125.09,52.54 | 113.66,52.54 SV10.3
  Bottom 1.016: 118.74,42.38 106.04,42.38 104.77,43.65 IC1.28 | 137.79,52.54 137.79,60.16 | 122.55,60.16 121.28,58.89 SV6.5 121.28,56.35 120.01,55.08
N$41
  Bottom 0.61: IC1.27 107.31,46.19 | SV6.6 123.82,56.35 120.01,52.54 116.2,52.54 SV10.4 116.2,50 114.93,48.73 112.39,48.73 111.12,47.46 108.58,47.46
  Bottom 0.813: 107.31,46.19 108.58,47.46
N$46
  Top 0.61: R20.1 29.84,67.78
  Top 0.813: 29.84,67.78 27.3,70.32 Q1.1
  Bottom 0.254: IC8.6 29.84,46.19
  Bottom 0.61: 14.6,54.45 13.33,54.45 13.33,46.19
  Bottom 0.813: 14.6,54.45 26.03,65.88 29.84,65.88 31.11,67.15 R20.1
  Bottom 1.016: 13.33,46.19 IC8.6
N$47
  Bottom 1.016: R19.2 C2.1
N$48
  Top 0.254: 24.76,72.86 Q1.2
  Top 0.61: 100.32,77.94 99.69,77.94 | 100.32,77.94 144.14,77.94 146.68,75.4 SV9.1 | 100.32,77.94 94.61,77.94 93.97,78.58 93.97,84.29 81.27,84.29 75.56,78.58 73.66,78.58 74.29,79.21 74.29,97.62 72.38,99.53 43.81,99.53 6.98,62.7 6.98,51.91 7.62,51.27 12.06,51.27 12.06,60.16 24.76,72.86
  Bottom 0.254: 145.41,72.86 142.87,72.86
  Bottom 0.813: 142.87,72.86 SV9.6 | SV9.1 145.41,72.86
N$49
  Bottom 0.61: R8.3 135.25,14.44 136.52,15.71 SV8.2
N$50  (via drill 0.6 pad 1.68)
  other vias: 43.18,54.45
N$51  (via drill 0.6 pad 1.68)
  other vias: 35.55,37.93
N$52  (via drill 0.6 pad 1.68)
  other vias: 103.5,84.29
N$54  (via drill 0.6 pad 1.68)
  Top 0.61: v58.41,37.93 59.05,38.57 v114.93,38.57
N$56
  Top 0.254: IC8.7 29.84,43.65
  Top 0.61: IC7.6 50.16,94.45 44.45,88.73 44.45,78.58 27.93,62.06 | 27.93,62.06 26.03,60.16 26.03,44.92 27.3,43.65 IC8.7 | 27.93,62.06 28.57,62.7
N$57
  Top 0.61: IC8.12 51.43,48.73 53.97,46.19 74.29,46.19 IC1.40
N$58
  Bottom 0.254: 123.82,22.06 130.17,22.06
  Bottom 0.61: D3.A 140.33,29.68 | 123.82,22.06 123.19,21.42 123.19,18.25 124.45,16.98 SV8.1
  Bottom 1.016: 130.17,22.06 131.44,23.33 131.44,29.68 132.71,30.95 | 132.71,30.95 132.71,44.28 137.16,48.73 144.78,48.73 144.78,41.11 146.04,39.84 C3.- | 132.71,30.95 D3.A
N$59
  Top 0.61: 33.65,43.02 33.65,42.38 | 33.65,43.02 33.65,50 32.38,51.27 IC8.4 | 8.89,50 8.25,50 | 8.89,50 6.98,50 5.08,51.91 5.08,63.34 9.52,67.78 10.16,67.78 13.33,70.95 13.33,72.86 41.27,100.8 78.1,100.8 82.55,96.36 | IC6.5 93.34,92.55 86.35,92.55 82.55,96.36 | 82.55,96.36 81.91,96.99 | 8.89,50 22.86,50 23.49,49.36 23.49,43.02 28.57,37.93 32.38,37.93 33.65,39.2 33.65,43.02
N$60
  Top 0.254: 36.19,44.92 41.27,44.92 | 113.66,32.22 113.66,27.14 | 125.72,98.26 126.36,98.26
  Top 0.61: 36.19,44.92 34.92,46.19 34.92,51.27 32.38,53.81 IC8.3 | 41.27,44.92 52.7,33.49 112.39,33.49 113.66,32.22 | 129.53,23.96 128.9,24.6 | 129.53,23.96 130.17,23.33 136.52,23.33 | 151.12,38.57 151.12,39.2 151.12,36.66 | 113.66,27.14 113.66,25.87 127.63,25.87 129.53,23.96 | 125.72,98.26 92.07,98.26 90.8,96.99 IC6.6
  Top 0.813: 136.52,23.33 149.85,36.66 151.12,36.66 | 151.12,39.2 151.12,76.04 129.53,97.62 128.9,97.62 128.27,98.26 125.72,98.26
N$61
  Top 0.254: 100.96,42.38 100.96,47.46 | 132.71,60.16 137.79,60.16
  Top 0.61: 57.15,42.38 56.51,42.38 | 57.15,42.38 100.96,42.38 | 100.96,47.46 108.58,55.08 130.17,55.08 132.71,57.62 132.71,60.16 | 137.79,60.16 141.6,63.97 141.6,65.24 142.87,65.24 149.22,71.59 149.22,75.4 141.6,83.02 106.04,83.02 102.23,79.21 99.69,79.21 99.05,79.84 99.05,81.12 98.42,81.75 IC6.12 | IC8.2 32.38,56.35 36.19,52.54 36.19,47.46 49.53,47.46 51.43,45.55 51.43,43.02 52.07,42.38 57.15,42.38
N$62
  Top 0.254: IC8.1 32.38,58.89
  Top 0.61: 32.38,58.89 60.32,86.83 IC7.13
N$63
  Bottom 0.254: C2.2 D3.C
  Bottom 1.016: D2.A 142.87,44.92 140.97,43.02 140.97,41.11 C2.2
N$65
  Bottom 1.016: R21.2 122.55,23.33 | 122.55,23.33 JP2.1 | 122.55,23.33 117.47,23.33 112.39,28.41 IC1.16
N$66
  Top 0.254: 98.42,94.45 IC6.3
  Top 0.61: 98.42,94.45 100.96,91.91 104.13,91.91 105.41,90.64 105.41,84.29 101.59,80.48 R10.1
N$70
  Top 0.254: 111.12,66.51 116.2,66.51 | IC1.33 92.07,46.19 | 120.01,70.32 IC3.7
  Top 0.61: 92.07,46.19 94.61,48.73 95.88,48.73 | 111.12,63.97 111.12,66.51 | 116.2,66.51 120.01,70.32 | R24.1 125.09,70.32 IC3.7
  Top 0.813: 95.88,48.73 111.12,63.97
  Bottom 0.254: 118.74,66.51 126.36,66.51
  Bottom 0.61: R24.1 126.36,66.51 | IC3.7 120.01,70.32
  Bottom 1.016: 120.01,70.32 118.74,69.05 118.74,66.51
N$71
  Top 0.61: R23.1 89.53,58.89 IC1.34
  Bottom 0.254: R23.1 85.72,66.51 | 86.99,70.32 IC4.7
  Bottom 0.61: 85.72,66.51 85.72,69.05
  Bottom 1.016: 85.72,69.05 86.99,70.32
N$72
  Top 0.61: R12.1 80.64,85.56 92.07,85.56 93.34,86.83 IC6.10
N$73
  Top 0.61: 104.13,69.05 97.15,69.05 81.91,53.81 IC1.37 | 104.13,69.05 108.58,69.05 112.39,72.86 IC3.1 | R25.1 75.56,67.78 73.66,69.69 73.66,74.77 81.91,83.02 92.7,83.02 92.7,76.67 96.52,72.86 102.86,72.86 104.13,71.59 104.13,69.05
  Bottom 1.016: R25.1 81.91,50 IC1.37
N$74
  Top 0.61: IC7.2 60.32,94.45 64.77,90.01 64.77,86.83 71.11,80.48 R13.1
N$76
  Top 0.61: IC1.38 79.37,46.19 75.56,50 R26.1 78.1,53.81 78.1,61.43 77.46,62.06 77.46,70.32 79.37,72.23 79.37,72.86 IC4.1
  Bottom 0.813: 79.37,47.46 R26.1
  Bottom 1.016: IC1.38 79.37,47.46
N$78
  Bottom 0.254: 38.73,91.91 52.7,91.91 | 53.97,93.18 53.97,98.26
  Bottom 0.61: 52.7,91.91 53.97,93.18
  Bottom 0.813: R14.1 38.73,91.91 | 53.97,98.26 56.51,98.26 57.78,96.99 IC7.3
N$81
  Top 0.61: IC1.39 76.83,46.19 69.21,53.81 69.21,67.78 65.4,71.59 65.4,74.13 64.13,75.4 59.05,75.4 | 59.05,75.4 56.51,75.4 55.24,74.13 IC5.1 | R28.2 59.05,51.27 59.05,75.4
  Bottom 0.61: 56.51,48.73 74.29,48.73
  Bottom 0.813: 74.29,48.73 76.83,46.19 | R28.2 56.51,48.73
  Bottom 1.016: 76.83,46.19 IC1.39
N$88
  Bottom 0.254: 107.31,23.33 Q2.1
  Bottom 1.016: C10.1 107.31,23.33 104.77,25.87 IC1.13
N$93
  Bottom 0.254: 112.39,23.33 Q2.2
  Bottom 1.016: C11.1 112.39,23.33 107.31,28.41 IC1.14
N$101
  Top 0.61: IC1.8 92.07,22.06 89.53,19.52 SV7.5
N$102  (1 unrouted)
  Bottom 0.254: 131.44,71.59 118.74,71.59 114.93,67.78 | 34.92,66.51 55.24,66.51 60.32,66.51 80.64,66.51 | 61.59,65.24 IC5.5
  Bottom 0.406: 83.18,66.51 80.64,66.51 IC4.3 | 55.24,66.51 IC5.3
  Bottom 0.61: R16.2 20.95,52.54 34.92,66.51 | 60.32,66.51 61.59,65.24 | 83.18,66.51 84.45,65.24 IC4.5 98.42,65.24 99.69,66.51 100.96,67.78 | 114.3,67.78 114.93,67.78
  Bottom 0.813: 131.44,71.59 R15.2
  Bottom 1.016: IC3.5 117.47,65.24 114.93,67.78 | 100.96,67.78 IC3.3
N$103
  Bottom 0.61: IC6.2 100.96,96.99
  Bottom 0.813: 102.23,98.26 117.47,98.26
  Bottom 1.016: 100.96,96.99 102.23,98.26 | 117.47,98.26 R9.1
N$111
  Bottom 0.61: SV1.3 120.01,79.21 121.28,77.94 134.62,77.94
  Bottom 1.016: SV1.3 R9.2 | IC3.6 122.55,67.78 124.45,69.69 130.17,69.69 132.07,67.78 135.25,67.78 135.25,77.31 134.62,77.94
N$113
  Bottom 0.813: 116.2,71.59 117.47,71.59
  Bottom 1.016: R10.2 IC3.2 114.93,70.32 116.2,71.59 | 117.47,71.59 SV1.2
N$115
  Top 0.61: R11.2 88.26,79.21 SV2.3
  Bottom 1.016: R11.2 92.07,70.32 89.53,67.78 IC4.6
N$116
  Top 0.61: SV2.2 85.72,79.21 81.91,75.4 82.23,75.08 | 82.23,75.08 83.18,74.13 83.18,71.59 81.91,70.32 IC4.2 | R12.2 75.56,74.13 76.19,74.77 76.19,75.4 82.55,75.4 82.23,75.08
  Bottom 1.016: R12.2 IC4.2
N$119
  Top 0.61: R13.2 62.86,79.21 SV3.3
  Bottom 0.61: IC5.6 64.13,67.78
  Bottom 1.016: 64.13,67.78 66.67,70.32 R13.2
N$128
  Top 0.61: IC5.2 52.07,70.32 52.07,76.04 53.34,77.31 59.05,77.31 59.69,77.94 60.32,77.94 SV3.2
  Bottom 1.27: R14.2 IC5.2
N$136
  Top 0.61: 121.28,15.71 88.26,15.71 86.99,16.98 SV7.6
  Top 0.813: 121.28,15.71 R8.2
VDD
  Top 0.406: R8.1 128.27,9.36
  Top 0.61: C18.1 101.59,21.42 121.91,21.42 126.36,16.98
  Top 0.813: 126.36,16.98 131.44,16.98 131.44,12.54 128.27,9.36
  Bottom 0.254: 85.72,10.63 85.72,15.71 | 122.55,72.86 IC3.8 | 118.74,86.83 118.74,83.02 118.74,77.94 | 103.5,86.83 IC6.14 | 116.2,77.94 116.2,83.02 | 99.69,28.41 IC1.11 99.69,30.95
  Bottom 0.406: 62.86,61.43 85.72,61.43 | 41.91,39.84 41.27,39.84 | 27.3,14.44 27.3,13.8 | 67.3,50.63 R26.2 | 34.29,74.77 33.02,73.5 33.02,67.15 20.95,55.08 17.77,55.08 17.14,54.45 17.14,51.27 25.39,51.27 27.93,53.81 27.93,57.62 36.19,57.62 37.46,58.89 39.37,58.89
  Bottom 0.61: 85.72,15.71 84.45,16.98 SV7.7 | C21.1 85.72,61.43 119.38,61.43 120.01,62.06 C15.1 | IC6.14 103.5,89.37 | 118.74,86.83 103.5,86.83 | 114.93,76.67 116.2,77.94 | 116.2,83.02 118.74,83.02 | 14.6,17.62 13.97,16.98 C9.1
  Bottom 0.813: 87.62,76.04 88.26,76.67 114.93,76.67 | 84.45,9.36 85.72,10.63 | 118.74,10 R21.1 | 67.3,50.63 54.61,50.63 51.43,47.46 | 41.91,43.65 41.91,44.92 | IC5.8 60.32,75.4 34.92,75.4 34.29,74.77 27.3,67.78 23.49,67.78 14.6,58.89 3.17,58.89 -0.01,55.71 -0.01,14.44 0.63,13.8 10.79,13.8 14.6,17.62 | 14.6,17.62 15.24,17.62 15.87,18.25 IC9.3 16.5,17.62 14.6,17.62
  Bottom 1.016: R7.1 R1.1 R2.1 R3.1 R4.1 R5.1 R6.1 R22.1 113.66,4.28 | C12.1 62.86,61.43 62.86,58.89 | 67.94,58.89 R23.2 | 62.86,58.89 67.94,58.89 | IC8.16 39.37,58.89 62.86,58.89 | 67.94,58.89 R25.2 | IC5.8 64.13,72.86 66.67,75.4 66.67,76.04 87.62,76.04 87.62,73.5 IC4.8 | 125.09,75.4 122.55,72.86 | 125.09,75.4 R24.2 | IC7.14 62.86,89.37 C17.1 67.94,90.64 102.23,90.64 103.5,89.37 C14.1 | 125.09,75.4 123.82,76.67 120.01,76.67 118.74,77.94 | C16.1 IC1.32 94.61,43.65 91.44,40.48 81.91,40.48 81.27,39.84 81.27,36.03 94.61,36.03 99.69,30.95 | C18.1 99.69,25.87 IC1.11 | IC10.3 48.89,23.33 48.89,13.8 | 48.89,13.8 48.89,8.72 49.53,8.09 65.4,8.09 66.67,9.36 84.45,9.36 | C8.1 15.24,25.23 21.58,25.23 23.49,23.33 23.49,18.25 | IC9.3 23.49,18.25 | 23.49,18.25 27.3,14.44 | 27.3,13.8 48.89,13.8
  Bottom 1.27: 113.66,4.28 R21.1 R8.1 141.6,9.36 C1.1 146.04,13.8 146.04,16.34 D1.A | 85.72,10.63 118.1,10.63 118.74,10 | 81.27,39.84 R27.2 R28.1 41.91,39.84 41.91,43.65 IC8.10 | 41.27,39.84 C13.1 | 51.43,47.46 44.45,47.46 41.91,44.92
VSS  (3 unrouted)
  Bottom 0.254: 47.62,94.45 IC7.7 | IC4.4 79.37,65.24 | 142.87,57.62 D2.C | 116.2,63.97 JP8.1 | 57.78,79.21 SV3.1 | 27.3,75.4 Q1.3 24.76,75.4 | JP5.1 86.99,52.54 | B1.- 47.62,4.28 | IC1.12 102.23,28.41 | C11.2 136.52,13.17 | 139.06,15.71 SV8.3 139.06,18.25 | 71.75,4.28 72.07,3.96
  Bottom 0.305: 85.72,33.49 85.72,22.06
  Bottom 0.406: 57.78,63.97 78.73,63.97 80,65.24 IC4.4 | 83.18,63.97 109.85,63.97 111.12,65.24 IC3.4 | 71.75,57.62 70.48,56.35 | 85.72,22.06 SV7.8 | 85.08,34.12 85.72,33.49 | 92.07,25.23 90.8,26.51 90.8,33.49 90.16,34.12 | 33.65,50 14.6,50
  Bottom 0.61: IC3.4 114.93,65.24 116.2,63.97 C15.2 | 71.75,57.62 81.91,57.62 86.99,52.54 | 97.15,50 95.88,51.27 JP5.1 | SV7.4 92.07,16.98 | 47.62,94.45 48.26,95.09 48.26,99.53 | 151.12,36.03 151.76,36.03 | 56.51,65.24 57.78,63.97 | IC4.4 80.64,63.97 C21.2 83.18,63.97 | 104.77,6.82 103.5,5.55 100.96,5.55 100.32,6.18 100.32,6.82 99.69,6.18 73.66,6.18 71.75,4.28
  Bottom 0.813: JP8.1 137.16,63.97 | 92.07,16.98 95.88,13.17 103.5,13.17 | 72.07,3.96 72.38,4.28 71.75,4.28 | 149.22,18.88 148.59,19.52 | 138.42,17.62 138.42,16.98 | C11.2 137.79,13.17 | 142.87,57.62 141.6,58.89 140.33,58.89 | 140.33,64.61 140.97,63.97 JP6.2 | C3.+ 146.68,43.65 146.68,55.71 146.04,56.35 142.23,56.35 | 46.35,4.92 B1.- | 95.24,40.48 95.24,41.74 | 97.15,43.65 IC1.31 | -2.54,11.27 6.34,11.27 | 34.92,51.27 33.65,50 | 14.6,50 R17.2
  Bottom 1.016: JP1.2 46.35,93.18 47.62,94.45 47.62,98.9 48.26,99.53 65.4,99.53 | C12.2 56.51,65.24 IC5.4 | JP6.2 137.16,63.97 137.16,81.75 126.36,92.55 | IC10.2 C20.1 C19.1 JP7.1 60.96,27.14 59.69,28.41 59.69,29.05 | IC7.10 IC7.11 IC7.12 SV3.1 | 56.51,77.94 R20.2 29.84,77.94 | 56.51,77.94 57.78,79.21 | 81.91,77.94 83.18,79.21 SV2.1 | 56.51,77.94 81.91,77.94 | 81.91,77.94 113.66,77.94 114.93,79.21 SV1.1 | C16.2 97.15,50 IC1.31 | 104.77,6.82 JP3.2 | C11.2 C10.2 103.5,13.17 C18.2 102.23,25.87 IC1.12 102.23,35.39 97.15,40.48 95.24,40.48 | 136.52,20.79 133.34,20.79 | B1.- 50.16,1.74 69.21,1.74 | 69.21,1.74 71.75,4.28 | 140.33,19.52 138.42,17.62 | 139.06,15.71 C1.2 137.79,13.17 | 140.33,64.61 140.33,58.89 | C14.2 109.21,92.55 126.36,92.55 | 7.62,79.21 6.98,79.21 | 6.34,11.27 15.24,11.27 17.14,9.36 26.66,9.36 27.3,8.72 27.3,3.01 44.45,3.01 46.35,4.92 | 88.26,99.53 121.91,99.53 126.36,95.09 126.36,92.55 | 88.26,99.53 65.4,99.53 | 133.34,20.79 JP2.2 | 133.34,20.79 133.34,27.77 142.87,27.77 151.12,36.03 | 151.76,36.03 151.76,41.11 150.49,42.38 147.31,42.38 | 95.24,41.74 97.15,43.65 | 69.21,1.74 137.79,1.74 | 65.4,99.53 66.67,98.26 C17.2 | 88.26,99.53 IC6.7 | 59.69,29.05 59.69,32.22 61.59,34.12 85.08,34.12 90.16,34.12 | 92.07,25.23 SV7.4 | C9.2 C8.2 | 59.69,29.05 13.97,29.05 C7.2 C6.2 R16.1 17.77,44.28 11.43,44.28 11.43,56.35
  Bottom 1.27: R16.1 20.95,41.11 IC8.8 31.11,36.03 C13.2 | 29.84,77.94 27.3,75.4 23.49,79.21 7.62,79.21 -0.01,79.21 -2.54,76.67 -2.54,11.27 | 139.06,18.25 136.52,20.79 | 149.22,18.88 149.22,13.17 137.79,1.74 | 148.59,19.52 140.33,19.52 | 70.48,56.35 70.48,54.45 52.7,54.45 49.53,51.27 IC8.13 34.92,51.27 | C9.2 C8.2 4.44,27.14 4.44,54.45 6.34,56.35 11.43,56.35

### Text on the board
Bottom: DROJO V2.1 | 18F4620 | (C) 2008 JWBrown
